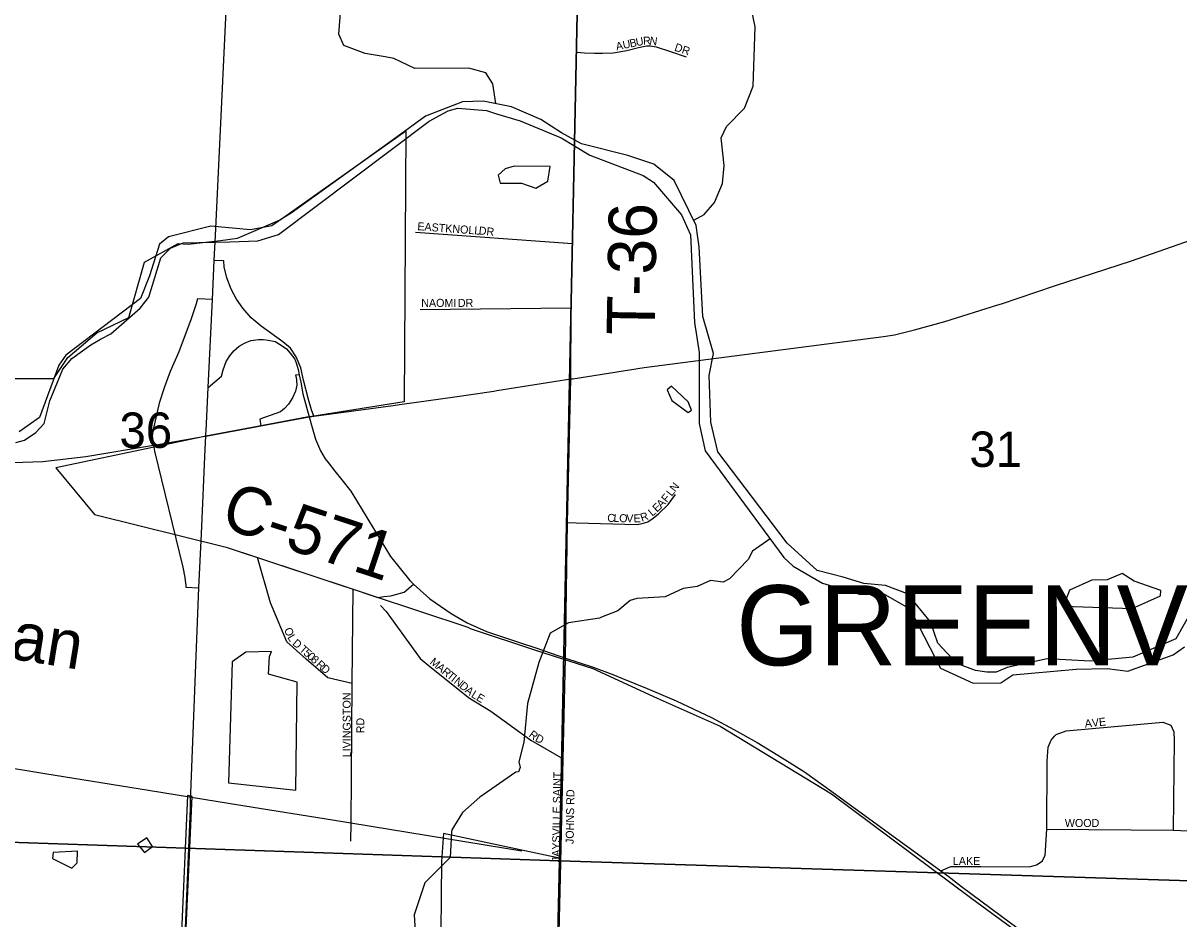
# Model space of a CAD drawing. Extents: x 0 to 1391, y -24 to 440.
# Drawn here: x 106.53 to 133.89, y 345.88 to 367.06 of the extents above; entities that cross this region are included whole.
import ezdxf

# ---------------------------------------------------------------- set-up
doc = ezdxf.new("R2010")
doc.units = 0
for name, color, linetype in [('GM_X_City_Street', 7, 'Continuous'), ('GM_X_City_Street_Text', 7, 'Continuous'), ('GM_X_Corporation', 7, 'Continuous'), ('GM_X_Corporation_Text', 7, 'Continuous'), ('GM_X_County_Road', 7, 'Continuous'), ('GM_X_County_Road_Text', 7, 'Continuous'), ('GM_X_Interchange_Ramps', 7, 'Continuous'), ('GM_X_Major_River', 7, 'Continuous'), ('GM_X_Minor_Lake', 7, 'Continuous'), ('GM_X_Minor_River', 7, 'Continuous'), ('GM_X_Rail_Line', 7, 'Continuous'), ('GM_X_Rail_Line_Text', 7, 'Continuous'), ('GM_X_Section', 7, 'Continuous'), ('GM_X_Section_Text', 7, 'Continuous'), ('GM_X_State_Route', 7, 'Continuous'), ('GM_X_Township_Road', 7, 'Continuous'), ('GM_X_Township_Road_Text', 7, 'Continuous'), ('GM_X_Township_Subdivision', 7, 'Continuous'), ('GM_X_Township_Subdivision_Text', 7, 'Continuous'), ('GM_X_US_Route', 7, 'Continuous')]:
    doc.layers.add(name, color=color, linetype=linetype)

msp = doc.modelspace()

# ---------------------------------------------------------------- linework, layer by layer
at = {"layer": 'GM_X_City_Street'}
for points in [[(114.325, 351.443), (113.749, 351.582), (113.237, 352.018), (112.775, 352.428), (112.39, 353.35), (112.081, 354.424)], [(114.296, 348.131), (114.296, 348.131), (114.325, 351.443), (114.344, 353.676)], [(114.99, 353.293), (115.124, 353.149), (115.932, 352.036), (116.161, 351.846), (117.104, 351.1), (117.604, 350.787), (118.548, 350.102), (119.316, 349.667)], [(119.258, 347.192), (119.258, 347.21), (119.316, 349.667), (119.372, 352.043)], [(114.293, 347.72), (114.296, 348.131)]]:
    msp.add_lwpolyline(points, dxfattribs=at)
at = {"layer": 'GM_X_Corporation'}
for points in [[(104.989, 358.656), (107.264, 358.657), (107.597, 359.156), (108.28, 359.741), (109.035, 360.099), (109.411, 361.409), (110.206, 361.85), (110.441, 361.833), (111.204, 361.923), (111.611, 361.98), (112.618, 362.41), (115.596, 364.516), (115.553, 358.107), (113.368, 357.763), (113.248, 357.744), (112.083, 357.526), (110.859, 357.298), (109.635, 357.038), (107.308, 356.544), (108.226, 355.44), (111.339, 354.669), (117.058, 352.779), (117.117, 352.745), (118.659, 352.233), (120.02, 351.801), (121.542, 351.099), (123.034, 350.436), (125.667, 348.838), (128.993, 346.361), (130.142, 345.517)], [(110.097, 339.093), (110.535, 348.775), (110.426, 348.793), (110.272, 345.388)], [(119.071, 339.472), (119.26, 347.31), (116.483, 347.895), (116.434, 347.232), (116.391, 342.253)]]:
    msp.add_lwpolyline(points, dxfattribs=at)
at = {"layer": 'GM_X_County_Road'}
for points in [[(111.339, 354.669), (112.081, 354.424), (114.344, 353.676), (114.762, 353.538), (114.929, 353.483), (115.076, 353.501)], [(115.076, 353.501), (115.076, 353.501), (115.242, 353.521), (115.557, 353.604), (115.778, 353.795)]]:
    msp.add_lwpolyline(points, dxfattribs=at)
at = {"layer": 'GM_X_Interchange_Ramps'}
for points in [[(113.413, 357.77), (113.36, 357.922), (113.289, 358.161), (113.175, 358.617), (113.106, 358.914), (113.001, 359.175), (112.862, 359.375), (112.681, 359.527), (112.173, 359.9), (111.933, 360.093), (111.734, 360.319), (111.583, 360.538), (111.456, 360.775), (111.36, 361.04), (111.297, 361.299), (111.282, 361.441), (111.058, 361.452)], [(111.014, 360.526), (110.663, 360.543), (110.632, 360.422), (110.515, 360.072), (110.218, 359.287), (110.019, 358.825), (109.873, 358.438), (109.755, 358.072), (109.606, 357.415), (109.591, 357.305), (109.621, 357.079)], [(113.067, 358.743), (112.98, 358.738), (112.999, 358.686), (113.008, 358.623), (113.013, 358.504), (112.984, 358.361), (112.909, 358.202), (112.816, 358.056), (112.72, 357.95), (112.63, 357.872), (112.139, 357.694), (112.163, 357.541)], [(109.621, 357.079), (109.648, 356.944), (110.319, 354.199), (110.366, 353.953), (110.385, 353.752), (110.385, 353.722), (110.695, 353.708)]]:
    msp.add_lwpolyline(points, dxfattribs=at)
at = {"layer": 'GM_X_Major_River'}
for points in [[(134.308, 353.36), (133.82, 352.503), (132.799, 352.066), (131.792, 351.971), (130.773, 352.028), (129.825, 351.826), (129.564, 351.717), (129.344, 351.713), (129.078, 351.756), (128.632, 351.916), (128.184, 352.403), (128.011, 352.901), (127.467, 353.564), (126.946, 353.764), (126.436, 353.811), (125.944, 353.957), (125.33, 354.12), (124.619, 354.764), (122.977, 356.922), (122.815, 357.624), (122.775, 358.734), (122.876, 359.248), (122.626, 360.127), (122.534, 361.777), (122.501, 361.998), (122.468, 362.279), (121.947, 363.345), (121.467, 363.726), (120.846, 363.935), (119.755, 364.213), (119.28, 364.473), (118.791, 364.786), (118.096, 365.087), (117.421, 365.221), (116.934, 365.207), (116.059, 364.866), (115.388, 364.377), (112.88, 362.57), (112.657, 362.437), (112.425, 362.267), (111.913, 362.177), (110.978, 362.263), (109.976, 362.008), (109.76, 361.837), (109.525, 361.09), (109.317, 360.554), (107.548, 359.212), (107.384, 358.971), (106.919, 357.734), (106.441, 357.401)], [(106.36, 357.144), (106.567, 357.201), (106.837, 357.379), (107.031, 357.595), (107.17, 358.132), (107.474, 358.879), (107.684, 359.133), (108.139, 359.459), (108.363, 359.592), (108.608, 359.716), (109.305, 360.326), (109.508, 360.581), (109.792, 361.51), (110.024, 361.741), (110.324, 361.872), (111.428, 361.89), (112.091, 361.916), (112.581, 362.066), (116.149, 364.743), (116.595, 364.993), (116.824, 365.05), (117.501, 364.999), (117.743, 364.919), (118.303, 364.757), (119.271, 364.351), (119.948, 363.944), (121.211, 363.457), (121.459, 363.301), (122.115, 362.529), (122.334, 362.054), (122.425, 359.986), (122.534, 359.278), (122.533, 357.591), (122.68, 356.95), (124.544, 354.424), (124.761, 354.222), (125.454, 353.822), (126.355, 353.547), (126.889, 353.575), (127.424, 353.269), (127.61, 353.045), (128.249, 351.81), (129.019, 351.453), (129.674, 351.464), (129.959, 351.648), (130.401, 351.686), (131.461, 351.787), (132.193, 351.797), (132.679, 351.734), (133.759, 352.124), (134.022, 352.309)]]:
    msp.add_lwpolyline(points, dxfattribs=at)
at = {"layer": 'GM_X_Minor_Lake'}
for points in [[(119.007, 363.673), (118.154, 363.681), (117.947, 363.616), (117.777, 363.467), (117.827, 363.277)], [(117.827, 363.277), (118.329, 363.283), (118.67, 363.162), (118.954, 363.324), (119.007, 363.673)], [(121.879, 358.477), (121.778, 358.388), (121.888, 358.142), (122.279, 357.854)], [(122.279, 357.854), (122.356, 357.913), (122.276, 358.105), (121.879, 358.477)], [(133.46, 353.642), (132.833, 353.866), (132.547, 354.047), (132.194, 353.901), (131.828, 353.893), (131.298, 353.652), (131.162, 353.275)], [(131.162, 353.275), (132.783, 353.221), (133.458, 353.52), (133.46, 353.642)], [(112.341, 351.664), (112.364, 352.081), (112.412, 352.202), (111.803, 352.19), (111.486, 351.96), (111.395, 349.098)], [(111.395, 349.098), (112.991, 348.924), (113.023, 351.476), (112.341, 351.664)], [(109.46, 347.797), (109.244, 347.649), (109.407, 347.448)], [(109.407, 347.448), (109.6, 347.589), (109.46, 347.797)], [(107.245, 347.45), (107.227, 347.306), (107.687, 347.077)], [(107.687, 347.077), (107.811, 347.204), (107.824, 347.477), (107.245, 347.45)]]:
    msp.add_lwpolyline(points, dxfattribs=at)
at = {"layer": 'GM_X_Minor_River'}
for points in [[(122.407, 362.404), (122.651, 362.541), (122.897, 362.822), (123.088, 363.272), (123.125, 363.697), (123.057, 364.354), (123.18, 364.617), (123.607, 365.051), (123.816, 365.576), (123.865, 366.975), (123.722, 367.673), (123.759, 367.878), (124.111, 368.352), (124.566, 368.74), (124.727, 368.97), (124.788, 369.204), (124.833, 369.401), (125.085, 369.62), (125.543, 369.863), (125.704, 370.108), (125.781, 370.357), (125.722, 370.626), (125.762, 370.898), (125.923, 371.151)], [(117.722, 365.161), (117.652, 365.632), (117.486, 365.889), (117.086, 366.002), (115.806, 365.993), (115.312, 366.231), (115.108, 366.269), (114.631, 366.347), (114.127, 366.539), (114.007, 366.803), (114.188, 369.141)], [(124.216, 354.869), (123.801, 354.572), (123.695, 354.382), (123.257, 353.918), (123.105, 353.842), (122.802, 353.879), (122.491, 353.742), (122.158, 353.689), (121.734, 353.498), (121.059, 353.459), (120.9, 353.406), (120.612, 353.162), (120.226, 353.017), (120.181, 352.987), (119.446, 352.879), (119.007, 352.638)], [(119.007, 352.638), (118.743, 351.944), (118.473, 350.972), (118.384, 350.061), (118.271, 349.59), (118.302, 349.461), (118.257, 349.355), (118.196, 349.347), (117.348, 348.753), (116.932, 348.396), (116.683, 347.986), (116.676, 347.932), (116.639, 347.332), (116.322, 347.006), (116.042, 346.732), (115.793, 345.972), (115.841, 345.198), (115.781, 344.894), (115.714, 344.378), (115.51, 344.006), (115.253, 343.709), (114.738, 343.343), (114.567, 343.163)]]:
    msp.add_lwpolyline(points, dxfattribs=at)
at = {"layer": 'GM_X_Rail_Line'}
msp.add_lwpolyline([(89.258, 352.201), (91.86, 351.785), (96.867, 350.97), (99.263, 350.583), (102.655, 350.043), (107.045, 349.317), (109.5, 348.924), (111.784, 348.552), (113.86, 348.217), (118.335, 347.484)], dxfattribs=at)
at = {"layer": 'GM_X_Section'}
for points in [[(99.755, 368.042), (119.659, 367.662), (119.229, 347.252), (99.204, 347.93)], [(119.659, 367.662), (139.822, 367.382), (139.614, 346.725), (134.652, 346.763), (119.229, 347.252)], [(99.204, 347.93), (119.229, 347.252), (118.783, 327.433), (98.654, 327.856)], [(119.229, 347.252), (134.652, 346.763), (134.552, 327.163), (118.78, 327.297), (118.783, 327.433)]]:
    msp.add_lwpolyline(points, close=True, dxfattribs=at)
at = {"layer": 'GM_X_State_Route'}
for points in [[(110.795, 357.287), (110.859, 357.298), (112.083, 357.526), (112.163, 357.541), (113.308, 357.753)], [(113.308, 357.753), (113.375, 357.504), (113.458, 357.224), (113.573, 356.948), (113.684, 356.76), (113.752, 356.674)], [(109.817, 357.114), (110.795, 357.287)], [(104.059, 356.694), (104.202, 356.68), (105.105, 356.635), (107.001, 356.696), (108.02, 356.814), (109.621, 357.079), (109.817, 357.114)], [(113.752, 356.674), (113.914, 356.468), (114.082, 356.264), (114.289, 355.991), (115.227, 354.452), (115.688, 353.878), (115.778, 353.795), (116.162, 353.45), (116.67, 353.1), (117.045, 352.88), (117.5, 352.678), (118.31, 352.407)], [(118.31, 352.407), (118.672, 352.286), (119.372, 352.043), (120.031, 351.83), (120.492, 351.655)], [(120.492, 351.655), (120.725, 351.566), (121.309, 351.326), (121.994, 351.032), (122.828, 350.638), (123.356, 350.357), (123.906, 350.047), (124.504, 349.69), (125.031, 349.356), (125.68, 348.891), (128.26, 347.016), (128.422, 346.893)], [(128.422, 346.893), (128.747, 346.645), (129.695, 345.941), (137.258, 340.351)]]:
    msp.add_lwpolyline(points, dxfattribs=at)
at = {"layer": 'GM_X_Township_Road'}
for points in [[(119.372, 352.043), (119.421, 355.251), (119.501, 358.654), (119.507, 360.328), (119.538, 361.855), (119.631, 366.374), (119.703, 369.893), (119.733, 371.367), (119.796, 374.459)], [(119.071, 339.309), (119.071, 339.322), (119.258, 347.192)]]:
    msp.add_lwpolyline(points, dxfattribs=at)
at = {"layer": 'GM_X_Township_Subdivision'}
for points in [[(119.631, 366.374), (119.82, 366.366)], [(119.82, 366.366), (120.058, 366.355), (120.249, 366.351), (120.499, 366.361), (120.825, 366.417), (121.101, 366.486), (121.288, 366.526), (121.387, 366.529), (121.515, 366.506), (121.857, 366.394), (122.229, 366.266)], [(115.825, 362.12), (119.538, 361.855)], [(115.932, 360.293), (119.507, 360.328)], [(119.624, 355.246), (121.071, 355.209), (121.19, 355.23), (121.323, 355.272), (121.446, 355.355), (121.576, 355.46), (121.799, 355.683), (121.977, 355.919)], [(119.421, 355.251), (119.624, 355.246)], [(130.947, 350.196), (130.989, 350.24), (131.225, 350.325), (133.513, 350.53), (133.698, 350.463), (133.77, 350.305), (133.777, 350.102), (133.757, 347.976)], [(128.64, 347.117), (128.744, 347.116), (129.201, 347.119), (130.353, 347.109), (130.523, 347.153), (130.653, 347.24), (130.723, 347.38), (130.766, 347.996), (130.772, 349.61), (130.799, 349.938), (130.864, 350.108), (130.947, 350.196)], [(130.766, 347.996), (133.757, 347.976), (135.037, 347.924), (138.153, 347.95), (138.389, 347.963), (139.74, 347.957)], [(128.26, 347.016), (128.49, 347.119), (128.64, 347.117)]]:
    msp.add_lwpolyline(points, dxfattribs=at)
at = {"layer": 'GM_X_US_Route'}
for points in [[(111.086, 362.045), (111.678, 374.506), (111.687, 374.701)], [(129.608, 360.402), (129.693, 360.428), (130.946, 360.852), (132.767, 361.444), (134.665, 362.108), (138.284, 363.484), (138.831, 363.68), (139.835, 363.949)], [(110.915, 358.443), (111.014, 360.526), (111.058, 361.452), (111.086, 362.045)], [(119.501, 358.654), (119.544, 358.655), (121.236, 358.916), (126.902, 359.653), (127.161, 359.695), (127.634, 359.807), (128.354, 360.007), (129.608, 360.402)], [(110.915, 358.443), (111.227, 358.713), (111.272, 358.861), (111.342, 359.058), (111.424, 359.199), (111.524, 359.31), (111.65, 359.421), (111.776, 359.492), (111.921, 359.555), (112.11, 359.585), (112.214, 359.585), (112.336, 359.566), (112.497, 359.532), (112.644, 359.444), (112.77, 359.362), (112.855, 359.258), (112.963, 359.117), (113.007, 359.01), (113.045, 358.869), (113.067, 358.743), (113.111, 358.572), (113.152, 358.294), (113.308, 357.753)], [(119.096, 358.589), (119.501, 358.654)], [(110.861, 357.351), (110.865, 357.424), (110.915, 358.443)], [(115.445, 358.045), (115.563, 358.064), (116.698, 358.216), (117.679, 358.362)], [(117.679, 358.362), (117.748, 358.372), (119.096, 358.589)], [(113.308, 357.753), (113.413, 357.77), (115.292, 358.019), (115.445, 358.045)], [(110.845, 356.986), (110.859, 357.298), (110.861, 357.351)], [(110.753, 354.983), (110.845, 356.986)], [(110.499, 348.652), (110.695, 353.708), (110.753, 354.983)], [(107.705, 327.774), (108.419, 329.346), (109.076, 331.156), (109.563, 333.102), (109.793, 334.399), (109.947, 335.757), (110.066, 338.096), (110.493, 348.491), (110.499, 348.652)]]:
    msp.add_lwpolyline(points, dxfattribs=at)

# ---------------------------------------------------------------- texts
at = {"layer": 'GM_X_City_Street_Text'}
for s, height, rotation, p in [('O', 0.189, 290.07, (112.709, 352.728)), ('L', 0.189, 301.0147, (112.783, 352.536)), ('D', 0.189, 319.4722, (112.894, 352.371)), ('T', 0.189, 318.1214, (113.057, 352.23)), ('5', 0.189, 318.1175, (113.157, 352.141)), ('0', 0.189, 318.1175, (113.243, 352.063)), ('8', 0.189, 318.1175, (113.33, 351.986)), ('R', 0.189, 318.1199, (113.454, 351.874)), ('D', 0.189, 318.121, (113.566, 351.774)), ('M', 0.189, 320.8993, (116.147, 351.927)), ('A', 0.189, 320.8998, (116.302, 351.801)), ('R', 0.189, 320.8984, (116.431, 351.696)), ('T', 0.189, 320.9024, (116.548, 351.601)), ('I', 0.189, 320.8897, (116.651, 351.517)), ('N', 0.189, 320.9117, (116.716, 351.465)), ('D', 0.189, 320.9067, (116.845, 351.36)), ('A', 0.189, 321.6367, (116.977, 351.253)), ('L', 0.189, 327.3698, (117.124, 351.137)), ('LIVINGSTON', 0.1894, 90, (114.289, 349.7)), ('E', 0.189, 329.4362, (117.243, 351.062)), ('RD', 0.1894, 90, (114.611, 350.267)), ('R', 0.189, 322.4136, (118.488, 350.204)), ('D', 0.189, 332.9601, (118.638, 350.092)), ('JAYSVILLE SAINT', 0.18939, 89.029, (119.239, 347.217)), ('JOHNS RD', 0.1894, 89.1316, (119.565, 347.646))]:
    msp.add_text(s, height=height, rotation=rotation, dxfattribs=at).set_placement(p)
at = {"layer": 'GM_X_Corporation_Text'}
msp.add_text('GREENVILLE', height=1.8939, rotation=0, dxfattribs=at).set_placement((123.41, 351.875))
at = {"layer": 'GM_X_County_Road_Text'}
msp.add_text('C-571', height=1.1364, rotation=341.7156, dxfattribs=at).set_placement((111.171, 355.159))
at = {"layer": 'GM_X_Rail_Line_Text'}
msp.add_text('R.J. Corman', height=1.13258, rotation=350.7396, dxfattribs=at).set_placement((99.468, 353.139))
at = {"layer": 'GM_X_Section_Text'}
for s, p in [('36', (108.816, 357.018)), ('31', (128.933, 356.568))]:
    msp.add_text(s, height=0.8371, rotation=0, dxfattribs=at).set_placement(p)
at = {"layer": 'GM_X_Township_Road_Text'}
msp.add_text('T-36', height=1.1364, rotation=88.9531, dxfattribs=at).set_placement((121.48, 359.678))
at = {"layer": 'GM_X_Township_Subdivision_Text'}
for s, height, rotation, p in [('A', 0.189, 11.9539, (120.584, 366.418)), ('U', 0.189, 11.9582, (120.747, 366.453)), ('B', 0.189, 11.9374, (120.91, 366.487)), ('U', 0.189, 11.9624, (121.057, 366.518)), ('R', 0.189, 2.5022, (121.212, 366.552)), ('N', 0.189, 352.0183, (121.352, 366.559)), ('DR', 0.1894, 341.5632, (121.936, 366.417)), ('EASTKNOLL', 0.1894, 355.8147, (115.861, 362.169)), ('DR', 0.1894, 353.9943, (117.312, 362.069)), ('NAOMI', 0.1894, 0, (115.958, 360.353)), ('DR', 0.1894, 0, (116.825, 360.352)), ('N', 0.189, 51.5556, (121.968, 355.963)), ('F', 0.189, 50.2385, (121.766, 355.714)), ('L', 0.189, 51.531, (121.885, 355.859)), ('E', 0.189, 44.1237, (121.539, 355.485)), ('A', 0.189, 45.9711, (121.64, 355.582)), ('C', 0.189, 358.7856, (120.359, 355.269)), ('L', 0.189, 358.8115, (120.509, 355.266)), ('O', 0.189, 358.7977, (120.642, 355.263)), ('V', 0.189, 358.7977, (120.809, 355.26)), ('E', 0.189, 1.5825, (120.986, 355.256)), ('R', 0.189, 18.7984, (121.18, 355.271)), ('L', 0.189, 40.3028, (121.427, 355.389)), ('AVE', 0.1894, 5.9031, (131.671, 350.402)), ('WOOD', 0.1894, 0, (131.191, 348.052)), ('LAKE', 0.1894, 0, (128.541, 347.153))]:
    msp.add_text(s, height=height, rotation=rotation, dxfattribs=at).set_placement(p)

doc.saveas('drawing.dxf')
